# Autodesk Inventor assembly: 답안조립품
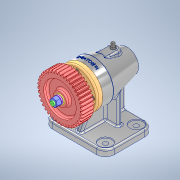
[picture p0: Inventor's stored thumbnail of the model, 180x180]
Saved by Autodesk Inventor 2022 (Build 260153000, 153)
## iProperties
Created: 2024-12
Part Number: 답안조립품
Document SubType Name: Assembly
Designer: PC-12
Author: PC-12
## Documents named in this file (15)
- C:\Users\PC-12\Desktop\741204V1016\답안조립품.iam
- C:\Users\PC-12\Desktop\741204V1016\본체.ipt
- C:\Users\PC-12\Desktop\741204V1016\스퍼기어.ipt
- C:\Users\PC-12\Desktop\741204V1016\스프링 와셔 M8.ipt
- C:\Users\PC-12\Desktop\741204V1016\실링.ipt
- C:\Users\PC-12\Desktop\741204V1016\앵귤러 볼 베어링 7003A.ipt
- C:\Users\PC-12\Desktop\741204V1016\앵귤러 볼 제어링 7204A.ipt
- C:\Users\PC-12\Desktop\741204V1016\오일 실 20 32 8.ipt
- C:\Users\PC-12\Desktop\741204V1016\육각 너트 M8.ipt
- C:\Users\PC-12\Desktop\741204V1016\육각 소켓 머리 볼트 M4x10.ipt
- C:\Users\PC-12\Desktop\741204V1016\축.ipt
- C:\Users\PC-12\Desktop\741204V1016\커버.ipt
- C:\Users\PC-12\Desktop\741204V1016\평와셔 M8.ipt
- C:\Users\PC-12\Desktop\741204V1016\평행 키 4x4x14.ipt
- C:\Users\PC-12\Desktop\741204V1016\그리스 니플 M6x0.75.ipt
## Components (1 placed, 1 different names)
1. 그리스 니플 M6x0.75:1
